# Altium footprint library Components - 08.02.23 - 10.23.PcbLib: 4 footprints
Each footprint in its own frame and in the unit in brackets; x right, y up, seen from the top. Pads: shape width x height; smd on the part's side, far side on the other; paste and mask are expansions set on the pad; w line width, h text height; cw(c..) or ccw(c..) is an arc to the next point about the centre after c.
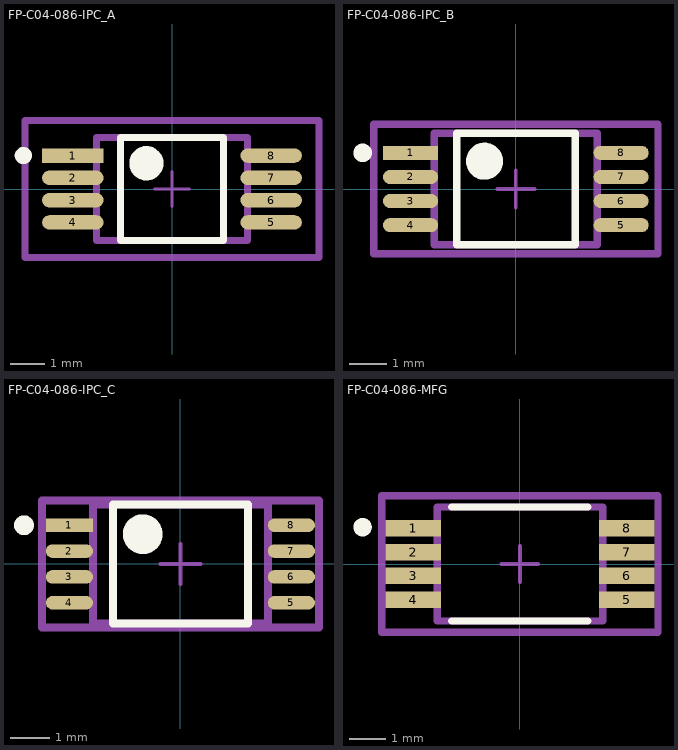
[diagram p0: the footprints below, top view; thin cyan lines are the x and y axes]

## FP-C04-086-IPC_A [mm]
pads (8):
  rect 1.788x0.421 smd paste+0 mask+0: 1(-2.891,0.975)
  rrect100% 1.788x0.421 smd paste+0 mask+0: 2(-2.891,0.325) 3(-2.891,-0.325) 4(-2.891,-0.975) 5(2.891,-0.975) 6(2.891,-0.325) 7(2.891,0.325) 8(2.891,0.975)
Top Overlay:
  circle w0.5: c-0.747,0.75 r0.25
  circle w0.25: c-4.335,0.975 r0.125
  lines w0.2: -1.497,-1.5 1.497,-1.5 1.497,1.5 -1.497,1.5 -1.497,-1.5
Top Assembly:
  lines w0.2: -4.285,-2 4.285,-2 4.285,2 -4.285,2 -4.285,-2
  text ".Designator" at 0,0.188 h1
Top 3D Body:
  lines w0.2: -2.2,-1.5 2.2,-1.5 2.2,1.5 -2.2,1.5 -2.2,-1.5
Top Courtyard:
  lines w0.2: -4.285,-2 4.285,-2 4.285,2 -4.285,2 -4.285,-2
Top Component Center:
  lines w0.1: -0.5,0 0.5,0 ; 0,-0.5 0,0.5
3D body "IC_Microchip_24FC08T-E-ST_eec.STEP": height 0.25, standoff 0, extent -4.285,-2 4.285,2

## FP-C04-086-IPC_B [mm]
pads (8):
  rect 1.488x0.381 smd paste+0 mask+0: 1(-2.841,0.975)
  rrect100% 1.488x0.381 smd paste+0 mask+0: 2(-2.841,0.325) 3(-2.841,-0.325) 4(-2.841,-0.975) 5(2.841,-0.975) 6(2.841,-0.325) 7(2.841,0.325) 8(2.841,0.975)
Top Overlay:
  circle w0.5: c-0.847,0.75 r0.25
  circle w0.25: c-4.135,0.975 r0.125
  lines w0.2: -1.597,-1.5 1.597,-1.5 1.597,1.5 -1.597,1.5 -1.597,-1.5
Top Assembly:
  lines w0.2: -3.835,-1.75 3.835,-1.75 3.835,1.75 -3.835,1.75 -3.835,-1.75
  text ".Designator" at 0,0.188 h1
Top 3D Body:
  lines w0.2: -2.2,-1.5 2.2,-1.5 2.2,1.5 -2.2,1.5 -2.2,-1.5
Top Courtyard:
  lines w0.2: -3.835,-1.75 3.835,-1.75 3.835,1.75 -3.835,1.75 -3.835,-1.75
Top Component Center:
  lines w0.1: -0.5,0 0.5,0 ; 0,-0.5 0,0.5
3D body "IC_Microchip_24FC08T-E-ST_eec.STEP": height 0.25, standoff 0, extent -3.835,-1.75 3.835,1.75

## FP-C04-086-IPC_C [mm]
pads (8):
  rect 1.188x0.341 smd paste+0 mask+0: 1(-2.791,0.975)
  rrect100% 1.188x0.341 smd paste+0 mask+0: 2(-2.791,0.325) 3(-2.791,-0.325) 4(-2.791,-0.975) 5(2.791,-0.975) 6(2.791,-0.325) 7(2.791,0.325) 8(2.791,0.975)
Top Overlay:
  circle w0.5: c-0.947,0.75 r0.25
  circle w0.25: c-3.935,0.975 r0.125
  lines w0.2: -1.697,-1.5 1.697,-1.5 1.697,1.5 -1.697,1.5 -1.697,-1.5
Top Assembly:
  lines w0.2: -3.485,-1.6 3.485,-1.6 3.485,1.6 -3.485,1.6 -3.485,-1.6
  text ".Designator" at 0,0.188 h1
Top 3D Body:
  lines w0.2: -2.2,-1.5 2.2,-1.5 2.2,1.5 -2.2,1.5 -2.2,-1.5
Top Courtyard:
  lines w0.2: -3.485,-1.6 3.485,-1.6 3.485,1.6 -3.485,1.6 -3.485,-1.6
Top Component Center:
  lines w0.1: -0.5,0 0.5,0 ; 0,-0.5 0,0.5
3D body "IC_Microchip_24FC08T-E-ST_eec.STEP": height 0.25, standoff 0, extent -3.485,-1.6 3.485,1.6

## FP-C04-086-MFG [mm]
pads (8):
  rect 1.5x0.45 smd paste+0 mask+0: 1(-2.9,0.975) 2(-2.9,0.325) 3(-2.9,-0.325) 4(-2.9,-0.975) 5(2.9,-0.975) 6(2.9,-0.325) 7(2.9,0.325) 8(2.9,0.975)
Top Overlay:
  circle w0.25: c-4.275,1 r0.125
  lines w0.2: -1.85,-1.55 1.85,-1.55 ; -1.85,1.55 1.85,1.55
Top Assembly:
  lines w0.2: -3.75,-1.85 3.75,-1.85 3.75,1.85 -3.75,1.85 -3.75,-1.85
  text ".Designator" at 0,0.188 h1
Top 3D Body:
  lines w0.2: -2.25,-1.55 2.25,-1.55 2.25,1.55 -2.25,1.55 -2.25,-1.55
Top Courtyard:
  lines w0.2: -3.75,-1.85 3.75,-1.85 3.75,1.85 -3.75,1.85 -3.75,-1.85
Top Component Center:
  lines w0.1: -0.5,0 0.5,0 ; 0,-0.5 0,0.5
3D body "IC_Microchip_24FC08T-E-ST_eec.STEP": height 0.25, standoff 0, extent -3.75,-1.85 3.75,1.85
